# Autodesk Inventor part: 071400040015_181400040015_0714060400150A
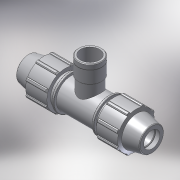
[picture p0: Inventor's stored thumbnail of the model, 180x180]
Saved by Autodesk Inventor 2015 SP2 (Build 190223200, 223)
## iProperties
Created: 2017-02
Part Number: 071400040015_181400040015_0714060400150A
Material: PVC-Piping
Description: PLASSON TEE WITH THREADED FEMALE OFFTAKE 40-1.1/2"-40
Document SubType Name: Modeling
Designer: KIM
Mass: 92.6774 g
Surface Area: 199.44 cm^2
Volume: 66.1981 cm^3
Density: 1.4 g/cm^3
Appearance: Smooth - White
Author: KIM
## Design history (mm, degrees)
derived "07140.ipt"
feature "Solid1::07140.ipt"
feature "Solid2::07140.ipt"
tag "TaggingFeature1"
body "Solid1"
other parameters: "d4" = 9.04167, "d5" = 26.04, "d7" = 82, "d11" = 3.61667, "d13" = 120 deg, "d15" = 12 deg, "d16" = 71.34, "d18" = 2, "d19" = 35 deg, "d20" = 17.5 deg, "d21" = 76.26, "d23" = 0, "d25" = 360 deg, "d27" = 1.64, "d33" = 0.8, "d42" = 39.06, "d43" = 2.46, "d46" = 1.2, "d68" = 6.51, "d76" = 44.845, "d80" = 1.34535, "d91" = 61.5, "d93" = 84, "d95" = 36, "d112" = 25, "d115" = 56.05625, "d116" = 135 deg, "d117" = 51.57175, "d118" = 217, "d119" = 36, "d121" = 0, "d122" = 36, "d124" = 0, "d128" = 0, "d129" = 4, "d130" = 7.5, "d131" = 0.3, "d132" = 0.3, "d133" = 56.05625, "E_" = 82, "l_" = 84, "l_2" = 25, "Rp_" = 44.845, "H_" = 217
